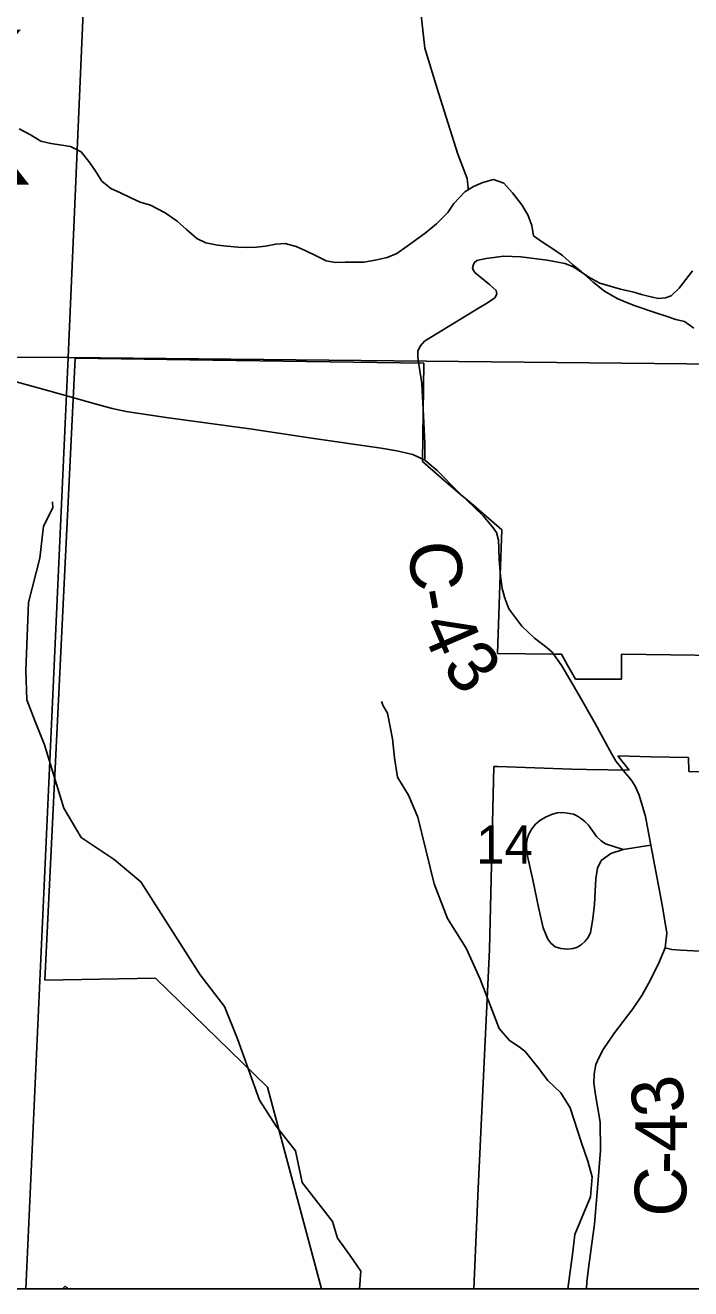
# Model space of a CAD drawing. Extents: x 2.1 to 8.9, y 14.1 to 20.9.
# Drawn here: x 3.368 to 4.099, y 14.1 to 15.488 of the extents above; entities that cross this region are included whole.
import ezdxf

# ---------------------------------------------------------------- set-up
doc = ezdxf.new("R2010")
doc.units = 0
for name, color, linetype in [('Default', 7, 'Continuous'), ('GM_X_City_Street', 7, 'Continuous'), ('GM_X_County_Road_Text', 7, 'Continuous'), ('GM_X_Interchange_Ramps', 7, 'Continuous'), ('GM_X_Minor_River', 7, 'Continuous'), ('GM_X_State_Shield', 7, 'Continuous'), ('GM_X_Township_Road_Text', 7, 'Continuous'), ('SH_Cut_Line', 7, 'Continuous'), ('SH_Data', 7, 'Continuous'), ('TX_P_Misc', 7, 'Continuous')]:
    doc.layers.add(name, color=color, linetype=linetype)

msp = doc.modelspace()

# ---------------------------------------------------------------- linework, layer by layer
at = {"layer": 'Default'}
for p, q in [((3.4148, 15.1232), (2.428, 15.1288)), ((3.3681, 14.1), (3.4148, 15.1232)), ((3.4148, 15.1232), (3.3681, 14.1)), ((3.4223, 15.1228), (3.389, 14.4392)), ((4.4256, 15.1132), (3.4148, 15.1232)), ((3.5737, 15.1206), (3.4223, 15.1228)), ((3.8059, 15.1172), (3.5737, 15.1206)), ((3.8044, 15.0089), (3.8059, 15.1172)), ((3.8279, 14.9887), (3.8044, 15.0089)), ((3.8459, 14.9733), (3.8279, 14.9887)), ((3.8516, 14.9685), (3.8459, 14.9733)), ((3.8606, 14.9607), (3.8516, 14.9685)), ((3.8664, 14.9558), (3.8606, 14.9607)), ((3.8917, 14.9341), (3.8664, 14.9558)), ((3.8897, 14.8843), (3.8917, 14.9341)), ((3.8867, 14.7981), (3.8897, 14.8843)), ((3.9476, 14.7973), (3.8867, 14.7981)), ((3.957, 14.7973), (3.9476, 14.7973)), ((3.9636, 14.7854), (3.957, 14.7973)), ((4.4177, 14.7917), (4.023, 14.7972)), ((4.023, 14.7972), (4.023, 14.77)), ((3.9727, 14.7699), (3.9636, 14.7854)), ((4.023, 14.77), (3.9727, 14.7699)), ((4.0317, 14.6698), (4.0192, 14.6857)), ((4.0192, 14.6857), (4.0552, 14.6845)), ((4.0552, 14.6845), (4.0969, 14.6836)), ((4.0969, 14.6836), (4.0972, 14.6685)), ((3.878, 14.4728), (3.8829, 14.674)), ((3.8829, 14.674), (3.8873, 14.6738)), ((3.8873, 14.6738), (3.9684, 14.671)), ((3.9684, 14.671), (3.985, 14.6707)), ((3.985, 14.6707), (4.0317, 14.6698)), ((4.0972, 14.6685), (4.214, 14.6654)), ((3.8654, 14.21), (3.878, 14.4728)), ((3.389, 14.4392), (3.5109, 14.4412)), ((3.5109, 14.4412), (3.634, 14.3213)), ((3.634, 14.3213), (3.6931, 14.1)), ((3.8609, 14.1), (3.8654, 14.21)), ((2.1, 14.1), (6.7017, 14.1)), ((3.167, 14.1), (3.3681, 14.1)), ((3.3681, 14.1), (4.3897, 14.1)), ((3.4115, 14.1029), (3.4086, 14.1)), ((3.4086, 14.1), (3.4147, 14.1)), ((3.6931, 14.1), (3.8609, 14.1))]:
    msp.add_line(p, q, dxfattribs=at)
msp.add_arc((3.4499, 14.1421), 0.0549, 225.573, 230.0477, dxfattribs=at)
at = {"layer": 'GM_X_City_Street'}
for p, q in [((3.8745, 15.2321), (3.8937, 15.2348)), ((3.8937, 15.2348), (3.9123, 15.2339)), ((3.9123, 15.2339), (3.9413, 15.2302)), ((3.8594, 15.2219), (3.8599, 15.2246)), ((3.86, 15.2196), (3.8594, 15.2219)), ((3.8599, 15.2246), (3.8613, 15.2273)), ((3.8619, 15.2168), (3.86, 15.2196)), ((3.8613, 15.2273), (3.8641, 15.2298)), ((3.8641, 15.2298), (3.8745, 15.2321)), ((3.9413, 15.2302), (3.9607, 15.2265)), ((3.9607, 15.2265), (3.9693, 15.2234)), ((3.9693, 15.2234), (3.9746, 15.2202)), ((3.9746, 15.2202), (3.9873, 15.2115)), ((4.0866, 15.1994), (4.1013, 15.2188)), ((3.8663, 15.2133), (3.8619, 15.2168)), ((3.8779, 15.2037), (3.8663, 15.2133)), ((3.9873, 15.2115), (3.9993, 15.2049)), ((3.9993, 15.2049), (4.0222, 15.1985)), ((3.8855, 15.197), (3.8779, 15.2037)), ((3.8838, 15.1888), (3.886, 15.193)), ((3.886, 15.193), (3.8855, 15.197)), ((4.0222, 15.1985), (4.0367, 15.1952)), ((4.0367, 15.1952), (4.0452, 15.1927)), ((4.0452, 15.1927), (4.0509, 15.191)), ((4.0509, 15.191), (4.0635, 15.1882)), ((4.0715, 15.1889), (4.0779, 15.1912)), ((4.0779, 15.1912), (4.0866, 15.1994)), ((3.8064, 15.1413), (3.8658, 15.1775)), ((3.8658, 15.1775), (3.8759, 15.1835)), ((3.8759, 15.1835), (3.8838, 15.1888)), ((4.0635, 15.1882), (4.0715, 15.1889)), ((3.7992, 15.1302), (3.8018, 15.1357)), ((3.8018, 15.1357), (3.8064, 15.1413)), ((3.7991, 15.1244), (3.7992, 15.1302)), ((3.7997, 15.1204), (3.7991, 15.1244)), ((3.8035, 15.0947), (3.7997, 15.1204)), ((3.8054, 15.0591), (3.8035, 15.0947)), ((3.807, 15.0286), (3.8054, 15.0591)), ((3.8069, 15.0107), (3.807, 15.0286)), ((3.9523, 14.6229), (3.9462, 14.6213)), ((3.9581, 14.6232), (3.9523, 14.6229)), ((3.9639, 14.6227), (3.9581, 14.6232)), ((3.9702, 14.6214), (3.9639, 14.6227)), ((3.9748, 14.6193), (3.9702, 14.6214)), ((3.9287, 14.6104), (3.9245, 14.6053)), ((3.9334, 14.6145), (3.9287, 14.6104)), ((3.9395, 14.6183), (3.9334, 14.6145)), ((3.9462, 14.6213), (3.9395, 14.6183)), ((3.9791, 14.6164), (3.9748, 14.6193)), ((3.9828, 14.6135), (3.9791, 14.6164)), ((3.9867, 14.6095), (3.9828, 14.6135)), ((3.9958, 14.5968), (3.9867, 14.6095)), ((3.9199, 14.5956), (3.9187, 14.5896)), ((3.9217, 14.6004), (3.9199, 14.5956)), ((3.9245, 14.6053), (3.9217, 14.6004)), ((4.0006, 14.5922), (3.9958, 14.5968)), ((3.9187, 14.5896), (3.9187, 14.5831)), ((3.9187, 14.5831), (3.9197, 14.5755)), ((4.0056, 14.5888), (4.0006, 14.5922)), ((4.0249, 14.5828), (4.0056, 14.5888)), ((4.0115, 14.5781), (4.0249, 14.5828)), ((4.0249, 14.5828), (4.0555, 14.5876)), ((3.9197, 14.5755), (3.9255, 14.5495)), ((3.9966, 14.5622), (4.0008, 14.5707)), ((4.0008, 14.5707), (4.0115, 14.5781)), ((3.995, 14.5507), (3.9966, 14.5622)), ((3.9255, 14.5495), (3.9324, 14.5175)), ((3.9933, 14.5226), (3.995, 14.5507)), ((3.9324, 14.5175), (3.937, 14.4966)), ((3.9915, 14.5065), (3.9933, 14.5226)), ((3.937, 14.4966), (3.942, 14.4841)), ((3.9889, 14.4914), (3.9915, 14.5065)), ((3.942, 14.4841), (3.9455, 14.4796)), ((3.9829, 14.4817), (3.9865, 14.4861)), ((3.9865, 14.4861), (3.9889, 14.4914)), ((3.9455, 14.4796), (3.9503, 14.4757)), ((3.9503, 14.4757), (3.9564, 14.474)), ((3.9564, 14.474), (3.9638, 14.4733)), ((3.9638, 14.4733), (3.9699, 14.4738)), ((3.9699, 14.4738), (3.9748, 14.4753)), ((3.9748, 14.4753), (3.9792, 14.4781)), ((3.9792, 14.4781), (3.9829, 14.4817)), ((4.0712, 14.4745), (4.0784, 14.4728)), ((4.0784, 14.4728), (4.0884, 14.4719)), ((4.0884, 14.4719), (4.1342, 14.4695))]:
    msp.add_line(p, q, dxfattribs=at)
at = {"layer": 'GM_X_Interchange_Ramps'}
for p, q in [((3.4577, 16.1051), (3.4148, 15.1232)), ((3.4148, 15.1232), (3.4577, 16.1051)), ((3.4148, 15.1232), (2.428, 15.1288)), ((4.4256, 15.1132), (3.4148, 15.1232))]:
    msp.add_line(p, q, dxfattribs=at)
at = {"layer": 'GM_X_State_Shield'}
for p, q in [((3.3509, 15.0983), (3.383, 15.0898)), ((3.383, 15.0898), (3.3936, 15.0868)), ((3.3936, 15.0868), (3.4469, 15.0716)), ((3.4469, 15.0716), (3.4631, 15.0672)), ((3.4631, 15.0672), (3.4785, 15.0639)), ((3.4785, 15.0639), (3.5226, 15.0573)), ((3.5226, 15.0573), (3.6172, 15.0446)), ((3.6172, 15.0446), (3.6849, 15.0343)), ((3.6849, 15.0343), (3.759, 15.0237)), ((3.759, 15.0237), (3.776, 15.0208)), ((3.776, 15.0208), (3.7937, 15.0168)), ((3.7937, 15.0168), (3.8069, 15.0107)), ((3.8069, 15.0107), (3.8205, 14.9991)), ((3.8205, 14.9991), (3.8434, 14.9758)), ((3.8434, 14.9758), (3.8711, 14.9492)), ((3.8711, 14.9492), (3.881, 14.9376)), ((3.881, 14.9376), (3.8856, 14.9312)), ((3.8856, 14.9312), (3.8877, 14.9242)), ((3.8877, 14.9242), (3.888, 14.9232)), ((3.888, 14.9232), (3.8888, 14.9019)), ((3.8888, 14.9019), (3.8901, 14.883)), ((3.8901, 14.883), (3.892, 14.8695)), ((3.892, 14.8695), (3.8949, 14.859)), ((3.8949, 14.859), (3.8993, 14.8473)), ((3.8993, 14.8473), (3.9134, 14.8281)), ((3.9134, 14.8281), (3.9276, 14.815)), ((3.9276, 14.815), (3.9413, 14.8042)), ((3.9413, 14.8042), (3.947, 14.7997)), ((3.947, 14.7997), (3.9575, 14.7844)), ((3.9575, 14.7844), (3.9762, 14.7527)), ((3.9762, 14.7527), (3.9942, 14.7211)), ((3.9942, 14.7211), (4.0103, 14.6913)), ((4.0103, 14.6913), (4.0168, 14.6798)), ((4.0168, 14.6798), (4.0186, 14.6776)), ((4.0186, 14.6776), (4.0271, 14.6671)), ((4.0271, 14.6671), (4.0324, 14.6612)), ((4.0324, 14.6612), (4.0352, 14.6571)), ((4.0352, 14.6571), (4.0386, 14.6514)), ((4.0386, 14.6514), (4.0424, 14.6423)), ((4.0424, 14.6423), (4.0495, 14.6188)), ((4.0495, 14.6188), (4.0555, 14.5876)), ((4.0555, 14.5876), (4.0678, 14.522)), ((4.0678, 14.522), (4.0728, 14.4907)), ((4.0728, 14.4907), (4.0712, 14.4745)), ((4.0712, 14.4745), (4.0635, 14.4563)), ((4.0635, 14.4563), (4.0529, 14.4353)), ((4.0529, 14.4353), (4.0455, 14.4222)), ((4.0455, 14.4222), (4.0356, 14.4077)), ((4.0356, 14.4077), (4.0156, 14.3812)), ((4.0156, 14.3812), (4.0029, 14.363)), ((4.0029, 14.363), (3.9984, 14.3544)), ((3.9949, 14.3463), (3.9929, 14.3361)), ((3.9984, 14.3544), (3.9949, 14.3463)), ((3.9929, 14.3361), (3.9928, 14.3258)), ((3.9928, 14.3258), (3.9945, 14.3132)), ((3.9945, 14.3132), (3.9995, 14.2829)), ((3.9995, 14.2829), (4.0001, 14.252)), ((4.0001, 14.252), (3.9968, 14.2106)), ((3.9968, 14.2106), (3.9933, 14.1709)), ((3.9933, 14.1709), (3.9916, 14.1579)), ((3.9916, 14.1579), (3.9872, 14.125)), ((3.9872, 14.125), (3.9849, 14.1078)), ((3.9849, 14.1078), (3.9847, 14.1))]:
    msp.add_line(p, q, dxfattribs=at)
at = {"layer": 'SH_Cut_Line'}
msp.add_line((2.1, 14.1), (6.7017, 14.1), dxfattribs=at)
at = {"layer": 'SH_Data'}
msp.add_line((2.1, 14.1), (8.9, 14.1), dxfattribs=at)
msp.add_line((2.1, 14.1), (8.9, 14.1), dxfattribs=at)
at = {"layer": 'TX_P_Misc'}
for p, q in [((3.8069, 15.4633), (3.8019, 15.5096)), ((3.8218, 15.4141), (3.8069, 15.4633)), ((3.843, 15.3468), (3.8218, 15.4141)), ((3.3735, 15.368), (3.3607, 15.3745)), ((3.3847, 15.3612), (3.3735, 15.368)), ((3.3958, 15.3585), (3.3847, 15.3612)), ((3.4076, 15.3569), (3.3958, 15.3585)), ((3.4172, 15.3553), (3.4076, 15.3569)), ((3.4292, 15.3493), (3.4172, 15.3553)), ((3.4375, 15.3389), (3.4292, 15.3493)), ((3.8533, 15.32), (3.843, 15.3468)), ((3.4443, 15.3288), (3.4375, 15.3389)), ((3.4518, 15.3173), (3.4443, 15.3288)), ((3.4616, 15.3092), (3.4518, 15.3173)), ((3.8546, 15.3097), (3.8533, 15.32)), ((3.8705, 15.3158), (3.8604, 15.3113)), ((3.8825, 15.3189), (3.8705, 15.3158)), ((3.8937, 15.315), (3.8825, 15.3189)), ((3.4724, 15.3042), (3.4616, 15.3092)), ((3.4836, 15.2988), (3.4724, 15.3042)), ((3.8507, 15.3053), (3.8389, 15.2928)), ((3.8604, 15.3113), (3.8507, 15.3053)), ((3.8545, 15.3077), (3.8546, 15.3097)), ((3.9032, 15.3043), (3.8937, 15.315)), ((3.9134, 15.2913), (3.9032, 15.3043)), ((3.494, 15.2942), (3.4836, 15.2988)), ((3.5051, 15.2908), (3.494, 15.2942)), ((3.5214, 15.2822), (3.5051, 15.2908)), ((3.8389, 15.2928), (3.832, 15.2827)), ((3.9203, 15.2801), (3.9134, 15.2913)), ((3.5346, 15.2731), (3.5214, 15.2822)), ((3.832, 15.2827), (3.8198, 15.2701)), ((3.9244, 15.2684), (3.9203, 15.2801)), ((3.5447, 15.2642), (3.5346, 15.2731)), ((3.5561, 15.2543), (3.5447, 15.2642)), ((3.8072, 15.2602), (3.7875, 15.2456)), ((3.8198, 15.2701), (3.8072, 15.2602)), ((3.9263, 15.2571), (3.9244, 15.2684)), ((3.5661, 15.2493), (3.5561, 15.2543)), ((3.5791, 15.2467), (3.5661, 15.2493)), ((3.5894, 15.2459), (3.5791, 15.2467)), ((3.643, 15.2479), (3.6316, 15.2457)), ((3.6532, 15.2486), (3.643, 15.2479)), ((3.6655, 15.2452), (3.6532, 15.2486)), ((3.9364, 15.2502), (3.9263, 15.2571)), ((3.9476, 15.2429), (3.9364, 15.2502)), ((3.6012, 15.2447), (3.5894, 15.2459)), ((3.6119, 15.2443), (3.6012, 15.2447)), ((3.6218, 15.2446), (3.6119, 15.2443)), ((3.6316, 15.2457), (3.6218, 15.2446)), ((3.6759, 15.2406), (3.6655, 15.2452)), ((3.6875, 15.2352), (3.6759, 15.2406)), ((3.6983, 15.2295), (3.6875, 15.2352)), ((3.7655, 15.2331), (3.7523, 15.2304)), ((3.776, 15.2376), (3.7655, 15.2331)), ((3.7875, 15.2456), (3.776, 15.2376)), ((3.9581, 15.2356), (3.9476, 15.2429)), ((3.9691, 15.2257), (3.9581, 15.2356)), ((3.7086, 15.2279), (3.6983, 15.2295)), ((3.7192, 15.2282), (3.7086, 15.2279)), ((3.7398, 15.2281), (3.7192, 15.2282)), ((3.7523, 15.2304), (3.7398, 15.2281)), ((3.9792, 15.2177), (3.9691, 15.2257)), ((3.9918, 15.2063), (3.9792, 15.2177)), ((4.0046, 15.1964), (3.9918, 15.2063)), ((4.0182, 15.1884), (4.0046, 15.1964)), ((4.0278, 15.1842), (4.0182, 15.1884)), ((4.0382, 15.1803), (4.0278, 15.1842)), ((4.0609, 15.1726), (4.0382, 15.1803)), ((4.0724, 15.1688), (4.0609, 15.1726)), ((4.0828, 15.1653), (4.0724, 15.1688)), ((4.0923, 15.163), (4.0828, 15.1653)), ((4.1028, 15.1557), (4.0923, 15.163)), ((3.3875, 14.9379), (3.3978, 14.9582)), ((3.3978, 14.9582), (3.3976, 14.9647)), ((3.3836, 14.9029), (3.3875, 14.9379)), ((3.3713, 14.854), (3.3836, 14.9029)), ((3.3681, 14.7795), (3.3713, 14.854)), ((3.3694, 14.7472), (3.3681, 14.7795)), ((3.3785, 14.7234), (3.3694, 14.7472)), ((3.7611, 14.7407), (3.7591, 14.7452)), ((3.7658, 14.7324), (3.7611, 14.7407)), ((3.3888, 14.6977), (3.3785, 14.7234)), ((3.7712, 14.7044), (3.7658, 14.7324)), ((3.4101, 14.6282), (3.3888, 14.6977)), ((3.7735, 14.6835), (3.7712, 14.7044)), ((3.7769, 14.6623), (3.7735, 14.6835)), ((3.789, 14.6423), (3.7769, 14.6623)), ((3.7992, 14.6182), (3.789, 14.6423)), ((3.4292, 14.5958), (3.4101, 14.6282)), ((3.8171, 14.5451), (3.7992, 14.6182)), ((3.4655, 14.5717), (3.4292, 14.5958)), ((3.4947, 14.5471), (3.4655, 14.5717)), ((3.56, 14.4448), (3.4947, 14.5471)), ((3.8318, 14.5069), (3.8171, 14.5451)), ((3.8524, 14.4742), (3.8318, 14.5069)), ((3.8678, 14.4402), (3.8524, 14.4742)), ((3.5867, 14.4102), (3.56, 14.4448)), ((3.8888, 14.3859), (3.8678, 14.4402)), ((3.6009, 14.3747), (3.5867, 14.4102)), ((3.9, 14.3727), (3.8888, 14.3859)), ((3.6252, 14.3071), (3.6009, 14.3747)), ((3.9107, 14.3657), (3.9, 14.3727)), ((3.9172, 14.3605), (3.9107, 14.3657)), ((3.9307, 14.344), (3.9172, 14.3605)), ((3.942, 14.3289), (3.9307, 14.344)), ((3.9566, 14.3151), (3.942, 14.3289)), ((3.6435, 14.2785), (3.6252, 14.3071)), ((3.9667, 14.2989), (3.9566, 14.3151)), ((3.9791, 14.2604), (3.9667, 14.2989)), ((3.6647, 14.2515), (3.6435, 14.2785)), ((3.9862, 14.2403), (3.9791, 14.2604)), ((3.6722, 14.2166), (3.6647, 14.2515)), ((3.9907, 14.2229), (3.9862, 14.2403)), ((3.9892, 14.2009), (3.9907, 14.2229)), ((3.7054, 14.1739), (3.6722, 14.2166)), ((3.9718, 14.1595), (3.9892, 14.2009)), ((3.7107, 14.1557), (3.7054, 14.1739)), ((3.7246, 14.1369), (3.7107, 14.1557)), ((3.9695, 14.1405), (3.9718, 14.1595)), ((3.7366, 14.1193), (3.7246, 14.1369)), ((3.9642, 14.1), (3.9695, 14.1405)), ((3.7352, 14.1), (3.7366, 14.1193))]:
    msp.add_line(p, q, dxfattribs=at)

# ---------------------------------------------------------------- texts
at = {"layer": 'GM_X_County_Road_Text'}
msp.add_text('14', height=0.04186, rotation=0, dxfattribs=at).set_placement((3.8634, 14.5672))
at = {"layer": 'GM_X_Minor_River'}
for s, rotation, p in [('C', 272.7018, (3.7897, 14.9205)), ('-', 280.1308, (3.7928, 14.8659)), ('4', 293.1205, (3.801, 14.8295)), ('3', 310.1476, (3.8243, 14.7817)), ('3', 100.119, (4.0943, 14.296)), ('4', 90.1632, (4.0953, 14.2502)), ('-', 88.9286, (4.0949, 14.2256)), ('C', 88.6221, (4.0937, 14.1786))]:
    msp.add_text(s, height=0.0568, rotation=rotation, dxfattribs=at).set_placement(p)
at = {"layer": 'GM_X_Township_Road_Text'}
msp.add_text('CREEK', height=0.17045, rotation=0, dxfattribs=at).set_placement((2.5892, 15.3133))

doc.saveas('drawing.dxf')
